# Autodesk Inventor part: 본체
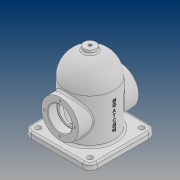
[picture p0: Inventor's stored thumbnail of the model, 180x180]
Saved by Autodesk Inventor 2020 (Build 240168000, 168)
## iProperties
Created: 2021-08
Part Number: 본체
Material: 일반
Document SubType Name: Modeling
Designer: PC312-
Density: 1 g/cm^3
Appearance: 기본값
Mass: 320.706 g
Surface Area: 800.755 cm^2
Volume: 320.706 cm^3
Author: PC312-
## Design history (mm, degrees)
sketch "스케치1"
  geometry: C1 r 40 at (0, 0); 1 further point
  constraints: 1 centre point, 1 coincident
  dimensions: "d0" = 80 diameter of C1
extrude "돌출1" new body sketch "스케치1" distance "d1" = 48; taper "d2" = 0 deg
sketch "스케치2"
  geometry: C1 r 40 at (0, 0) reference; 1 further point
extrude "돌출2" join sketch "스케치2" distance "d3" = 36; taper "d4" = 0 deg
sketch "스케치3"
  geometry: L1 (-40, -48)-(40, -48) reference; L2 (0, -4)-(0, 76); A1 r 40 centre (0, 36) between (0, -4) and (0, 76); 1 further point
  constraints: 2 end point, 2 point on circle, 1 centre point, 1 midpoint, 1 vertical, 1 vertical alignment
  dimensions: "d5" = 80 diameter of A1; "d7" = 84 distance from line of L1 A1.centre
revolve "회전1" sketch "스케치3" stored, may be unused: angle "d8" = 280 deg
feature "쉘1" dims "d10" = 8
sketch "스케치4"
  geometry: L1 (55, 55)-(-55, 55); L2 (-55, 55)-(-55, -55); L3 (-55, -55)-(55, -55); L4 (55, -55)-(55, 55); L5 (55, 55)-(-55, -55); L6 (-55, 55)-(55, -55); C1 r 32 at (0, 0) reference; 1 further point
  constraints: 12 end point, 2 midpoint, 2 parallel, 1 horizontal, 1 perpendicular
  dimensions: "d11" = 110 distance of L3.end L2.end; "d12" = 110 distance of L2.end L1.end
extrude "돌출3" join sketch "스케치4" distance "d13" = 10; taper "d14" = 0 deg
node "작업 평면2"
sketch "스케치5"
  geometry: C1 r 31 at (0, 0); 1 further point
  constraints: 1 centre point, 1 coincident
  dimensions: "d16" = 62 diameter of C1
extrude "돌출4" join sketch "스케치5" stored distance "d17" = 10; taper "d18" = 0 deg
sketch "스케치6" dims "d19" = 51
  geometry: 3 further points
  constraints: 2 vertical alignment, 1 coincident, 2 other
hole "구멍1" sketch "스케치6" at (0, 25.5) diameter "d20" = 3.242; stored, may be unused: countersink angle "d24" = 90 deg, drill point angle "d26" = 118 deg; dims "d21" = 8, "d22" = 4, "d23" = 2, "d25" = 10
sketch "스케치7"
  geometry: C1 r 31 at (0, 0) reference; 2 further points
  constraints: 1 coincident
hole "구멍2" sketch "스케치7" at (0, 0) diameter "d30" = 33; stored, may be unused: countersink angle "d34" = 90 deg, drill point angle "d36" = 0 deg; dims "d31" = 8, "d32" = 40, "d33" = 15, "d35" = 10
node "작업 평면3"
sketch "스케치8"
  geometry: C1 r 10 at (0, 0); 1 further point
  constraints: 1 centre point, 1 coincident
  dimensions: "d38" = 20 diameter of C1
extrude "돌출5" join sketch "스케치8" stored distance "d39" = 10; taper "d40" = 0 deg
sketch "스케치9"
  geometry: C1 r 10 at (0, 0) reference; 2 further points
  constraints: 1 coincident
hole "구멍3" sketch "스케치9" at (0, 0) diameter "d41" = 5.1881; stored, may be unused: countersink angle "d45" = 90 deg, drill point angle "d47" = 0 deg; dims "d42" = 12, "d43" = 40, "d44" = 15, "d46" = 16
fillet "모깎기1" dims "d48" = 12
sketch "스케치10"
  geometry: A1 r 12 centre (-43, -43) between (-55, -43) and (-43, -55) reference; A2 r 12 centre (-43, 43) between (-43, 55) and (-55, 43) reference; A3 r 12 centre (43, 43) between (55, 43) and (43, 55) reference; A4 r 12 centre (43, -43) between (43, -55) and (55, -43) reference; 5 further points
  constraints: 4 coincident
hole "구멍4" sketch "스케치10" at (-43, -43), (-43, 43), (43, 43), (43, -43) diameter "d49" = 9; stored, may be unused: countersink angle "d53" = 90 deg, drill point angle "d55" = 0 deg; dims "d50" = 12, "d51" = 40, "d52" = 15, "d54" = 16
node "작업 평면4"
sketch "스케치11"
  geometry: L1 (-48, -43)-(-48, 43) reference; 2 further points
  constraints: 1 other
  dimensions: "d57" = 48 distance from line of L1 point (0, -0.099)
feature "엠보싱1" sketch "스케치11" dims "d58" = 0.5, "d59" = 0
fillet "모깎기2" dims "d60" = 0.3
fillet "모깎기3" dims "d61" = 3
chamfer "모따기1" distance "d62" = 1; stored, may be unused: second distance "d63" = 2, angle "d64" = 45 deg
node "솔리드1"
pattern_circular "원형 패턴1" dims angle "d28" = 360 deg
mirror "미러1"
feature "A9D066F2-1C7D-4E18-AEED-F7BC21143FA4" dims "d49" = 9, "d50" = 12, "d51" = 40, "d52" = 15, "d53" = 90 deg, "d54" = 16, "d55" = 0
other parameters: "d37" = -129, "d56" = 64.75
